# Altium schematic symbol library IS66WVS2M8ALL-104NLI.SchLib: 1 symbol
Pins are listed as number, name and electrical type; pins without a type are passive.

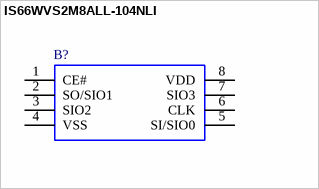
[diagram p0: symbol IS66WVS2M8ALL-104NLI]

## IS66WVS2M8ALL-104NLI
designator B?
SRAM 16Mb, SerialRAM, 1.65V-1.95V, 104MHz, 8 pin SOIC 150 mil, RoHS; Manufacturer_Name: Integrated Silicon Solution Inc.; Geometry.Height: 1.75mm
footprint SOIC127P600X175-8N
pins: 1 CE#, 2 SO/SIO1, 3 SIO2, 4 VSS, 5 SI/SIO0, 6 CLK, 7 SIO3, 8 VDD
